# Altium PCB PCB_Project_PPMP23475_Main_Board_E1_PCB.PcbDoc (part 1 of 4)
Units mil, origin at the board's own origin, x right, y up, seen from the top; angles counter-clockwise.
Board outline 10826.77 x 2559.06 mil, 6 copper layers (Top Layer, Signal Layer 1, Signal Layer 2, Signal Layer 3, Signal Layer 4, Bottom Layer), stack 65.535 mil thick; 162 components, 91 nets, 425 pads, 676 vias.
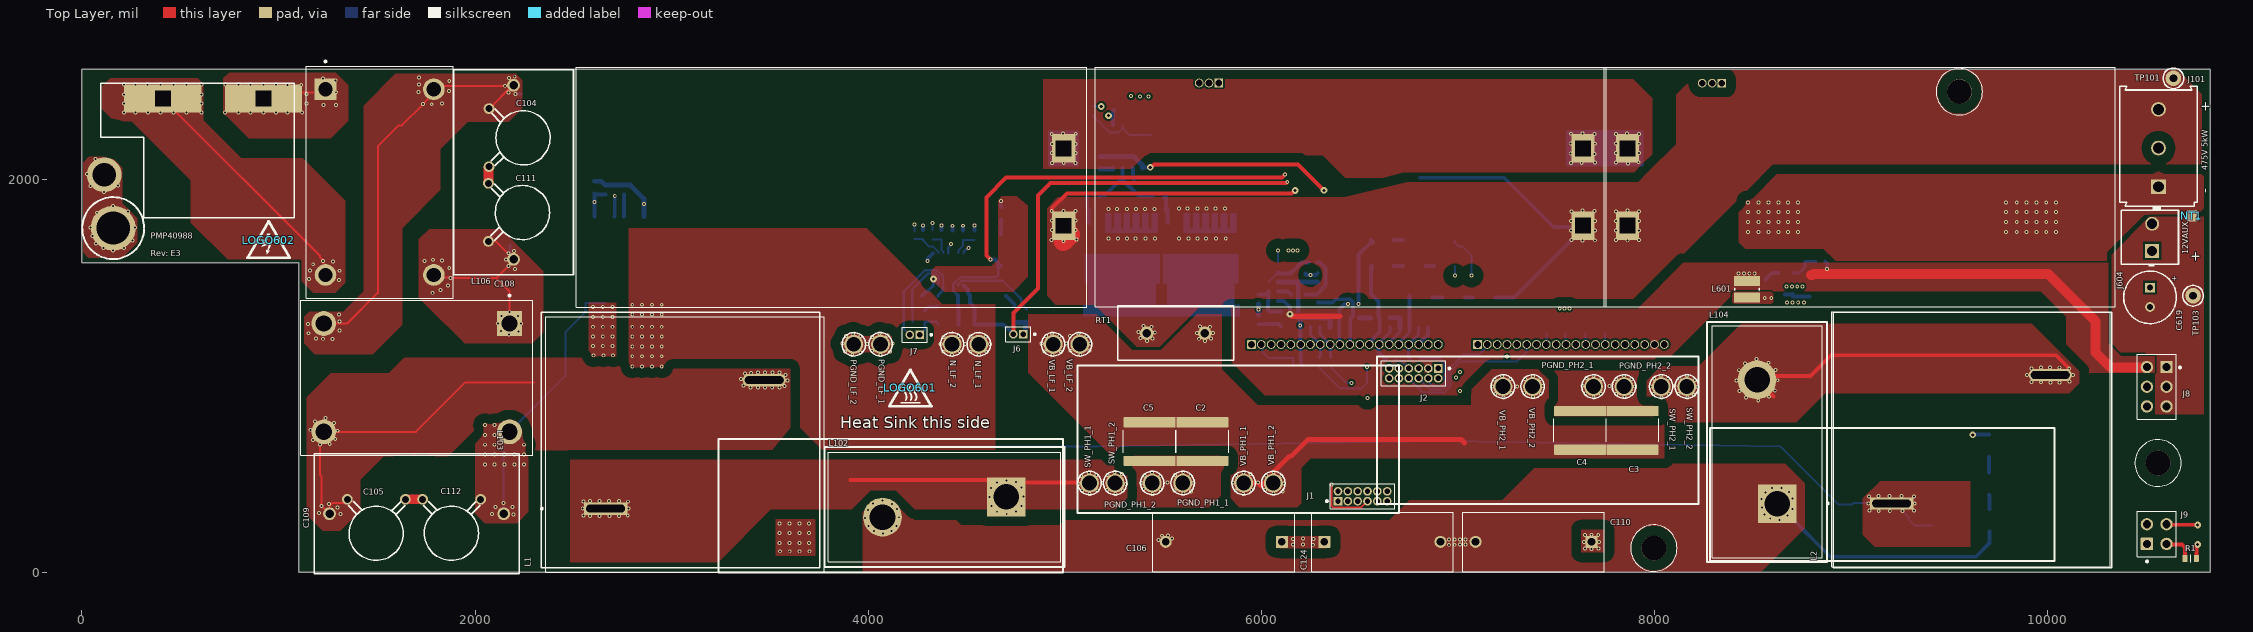
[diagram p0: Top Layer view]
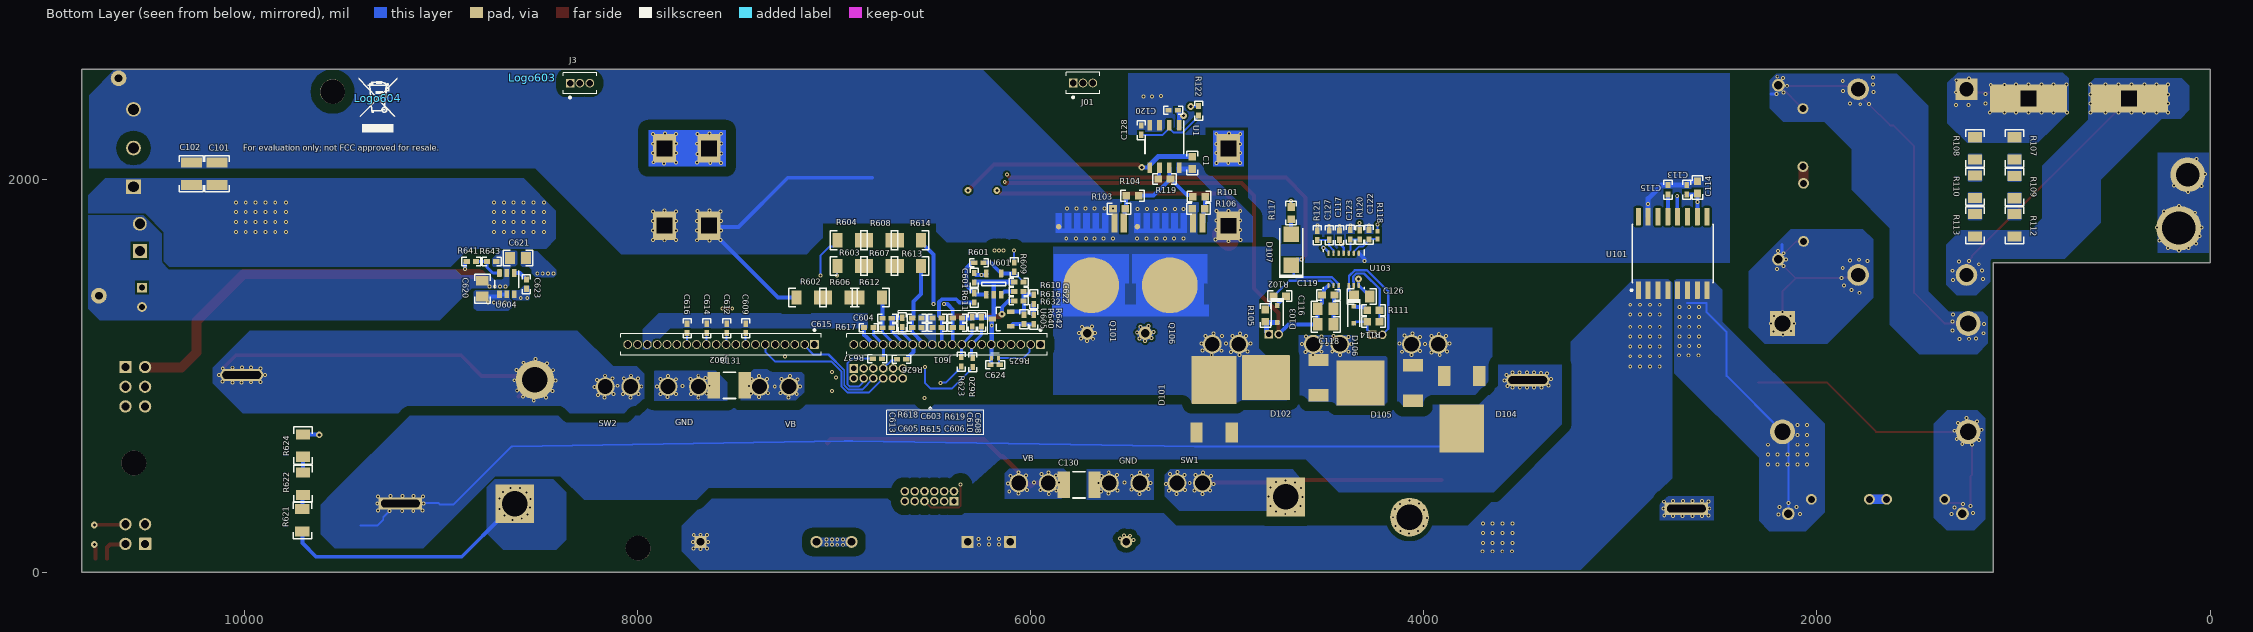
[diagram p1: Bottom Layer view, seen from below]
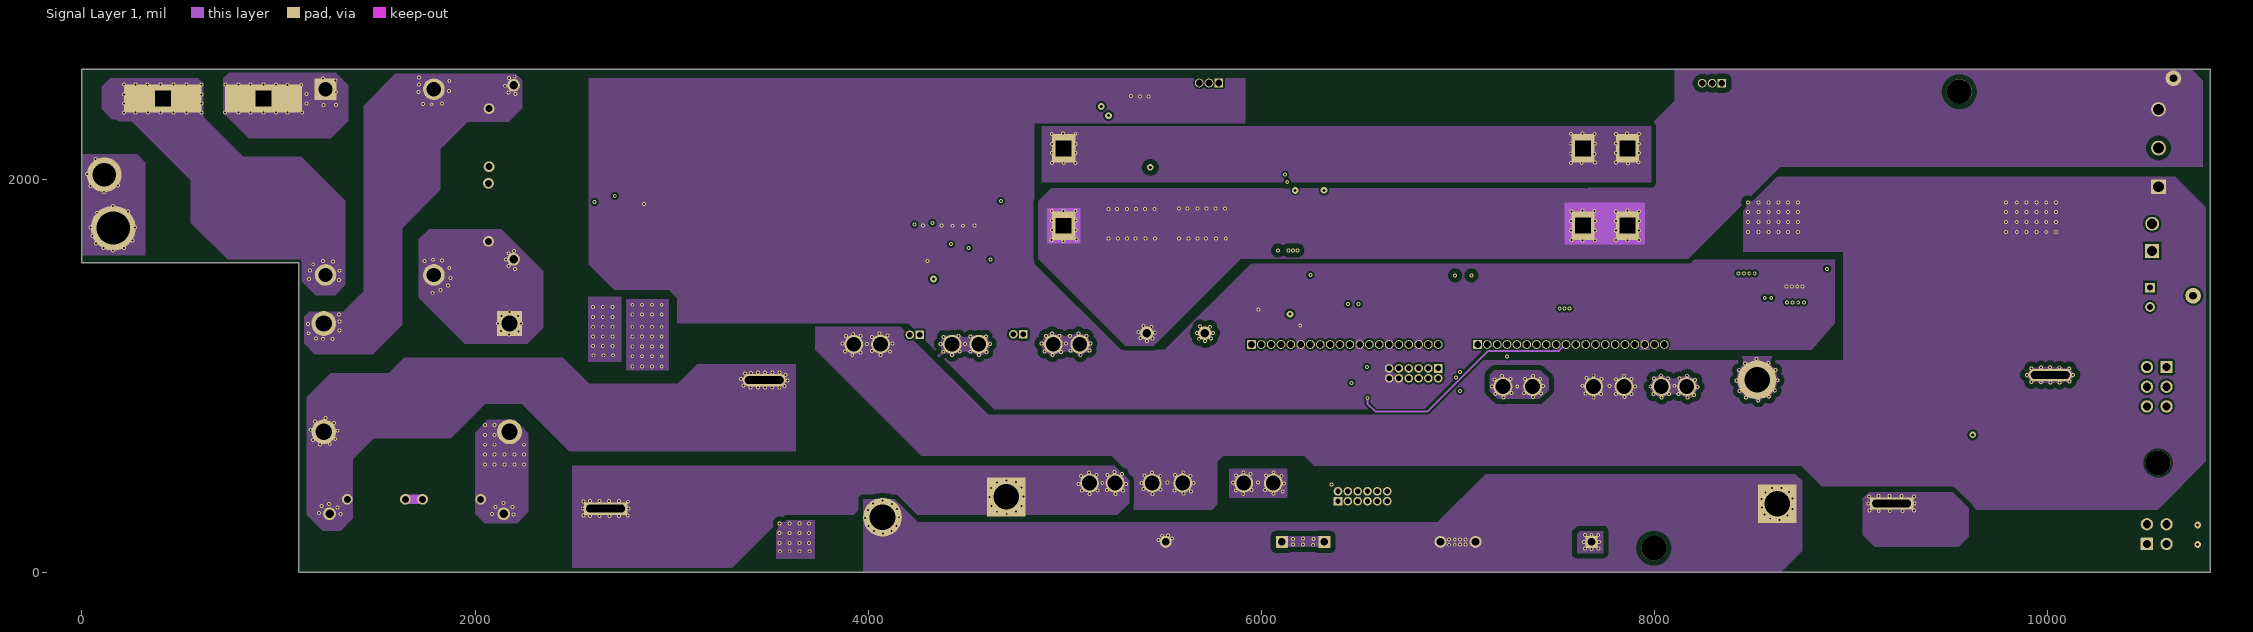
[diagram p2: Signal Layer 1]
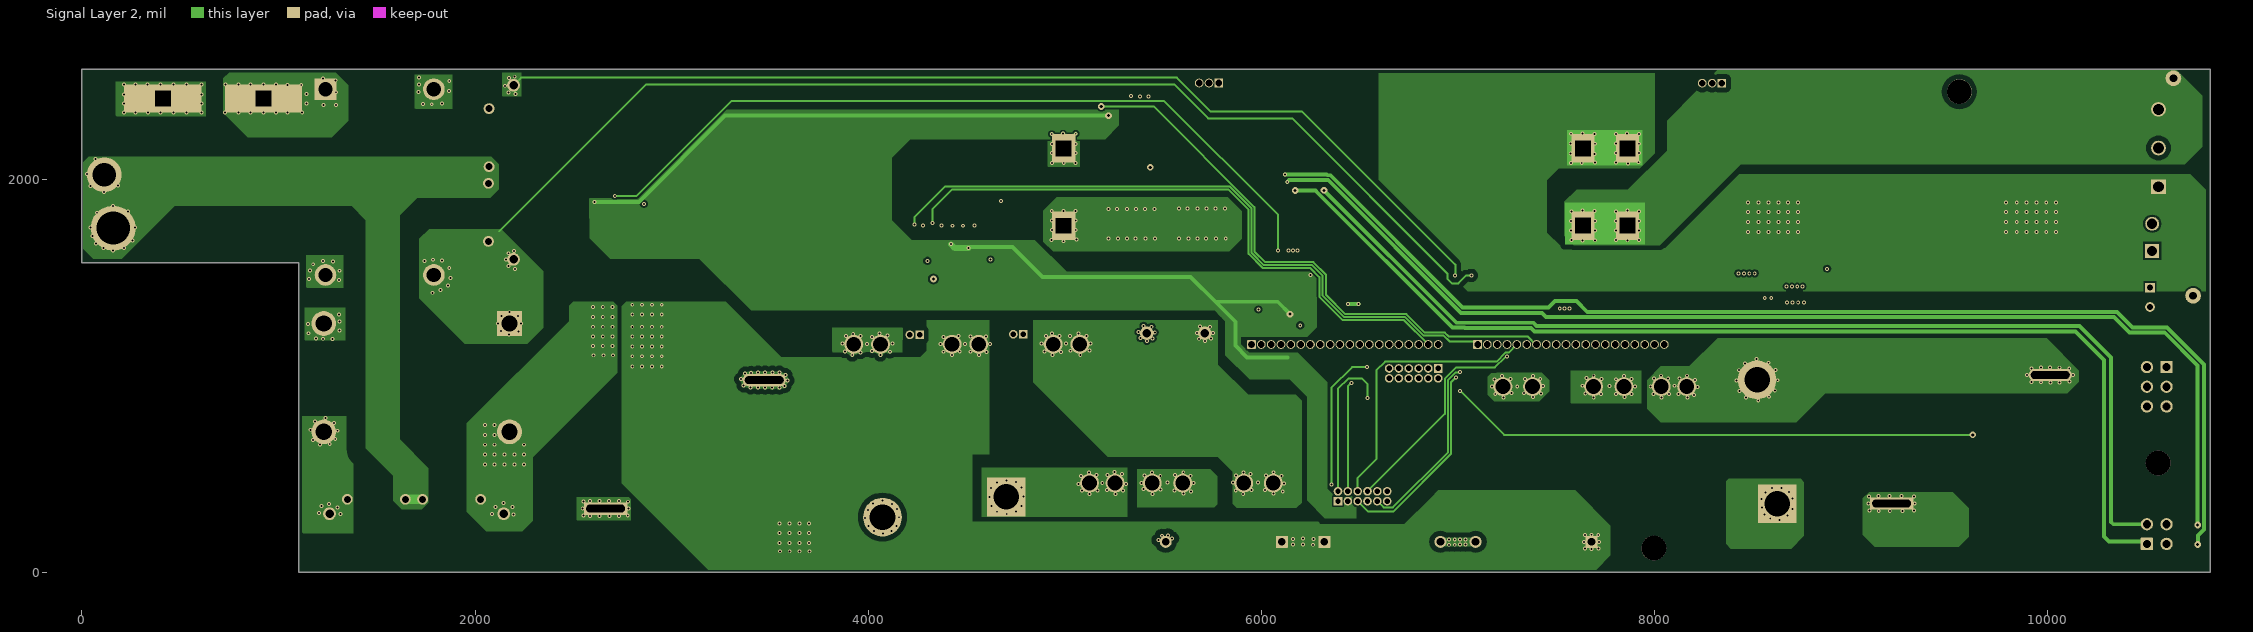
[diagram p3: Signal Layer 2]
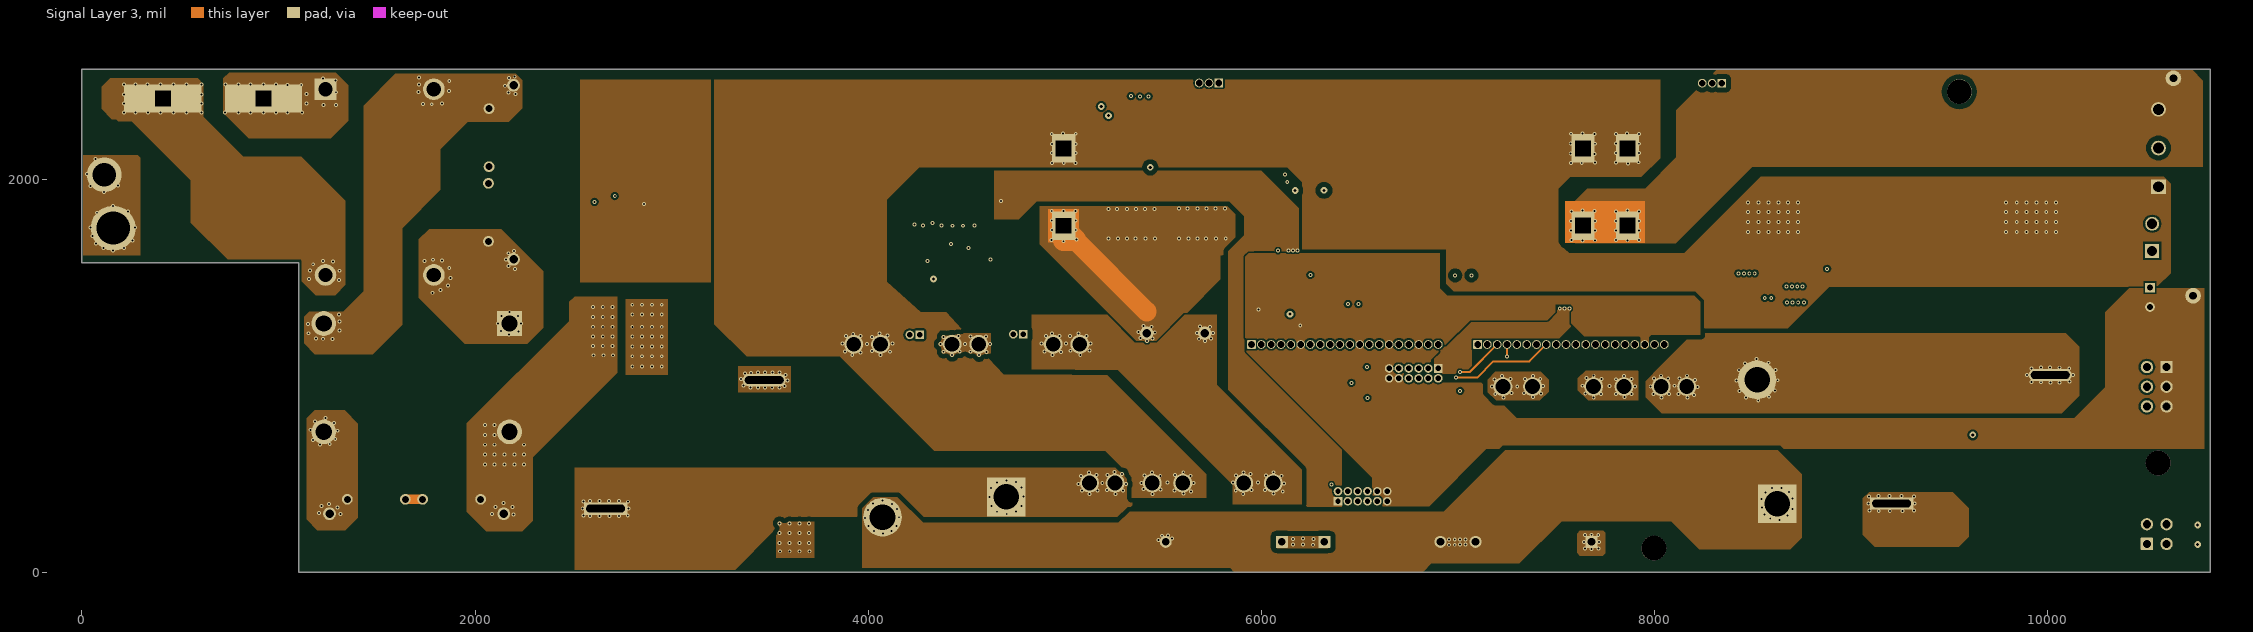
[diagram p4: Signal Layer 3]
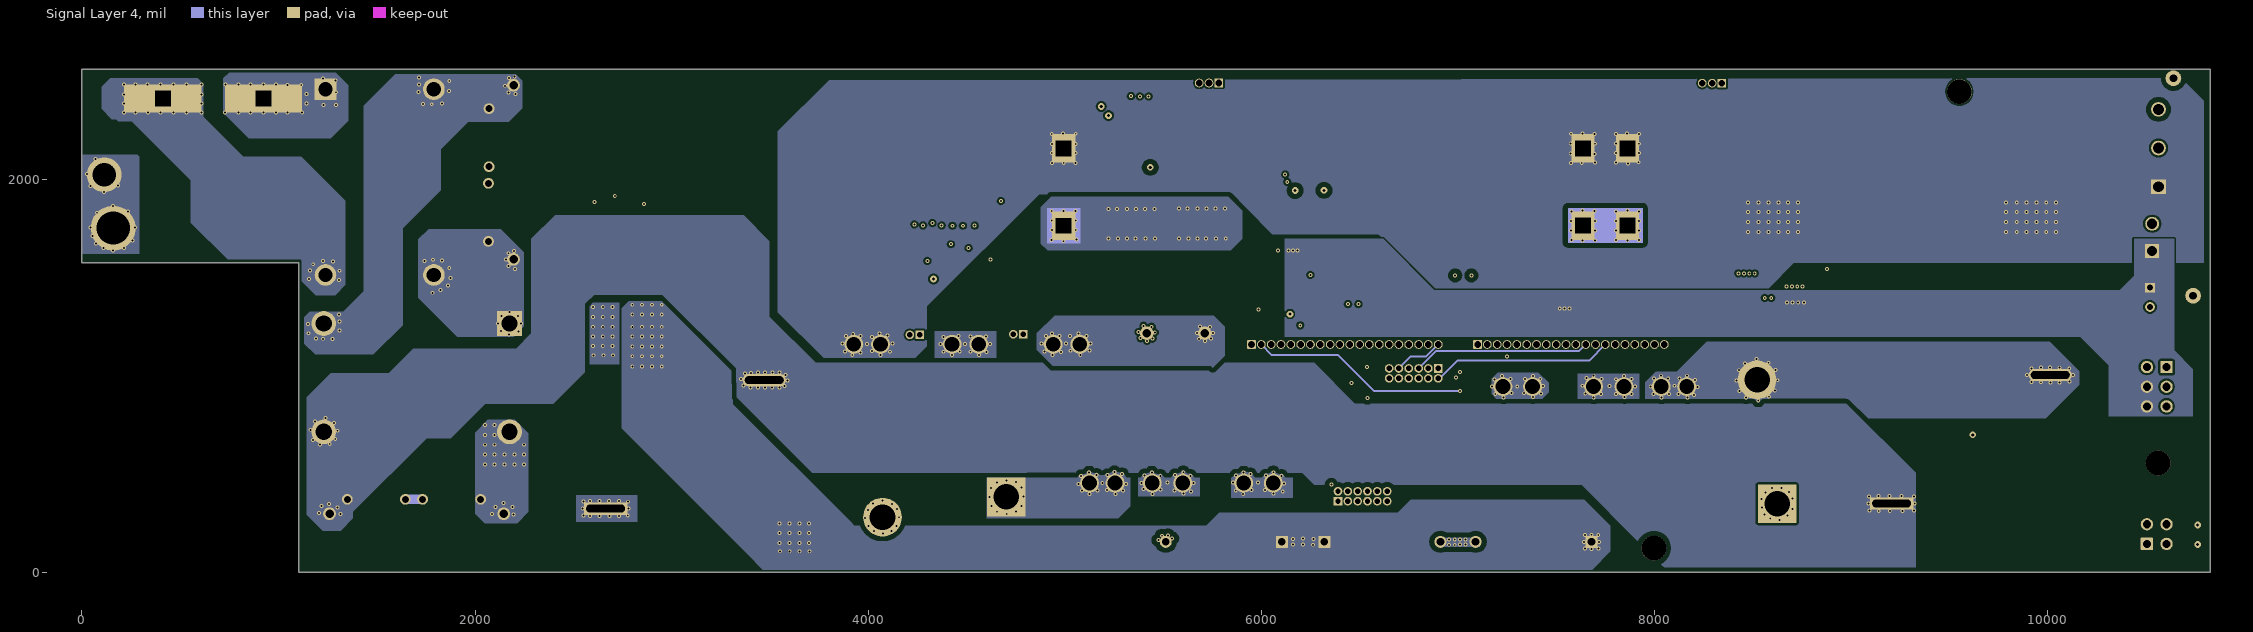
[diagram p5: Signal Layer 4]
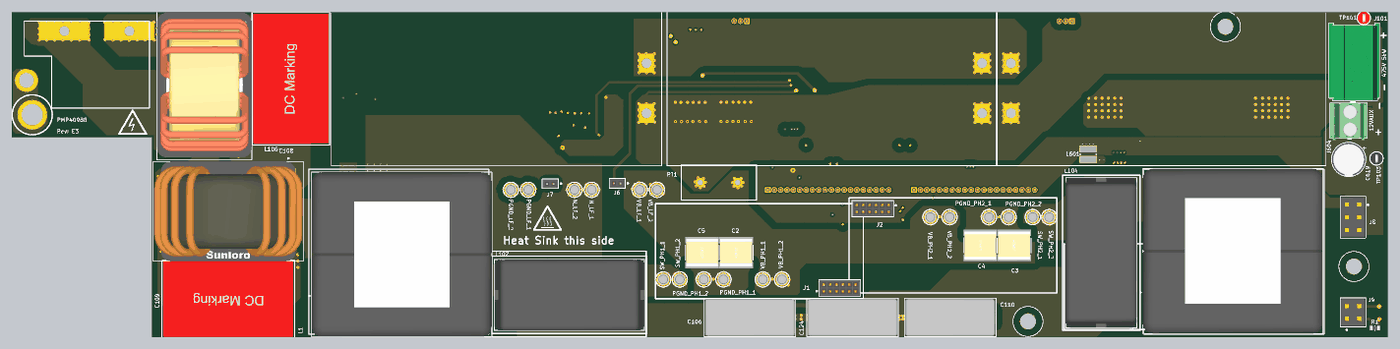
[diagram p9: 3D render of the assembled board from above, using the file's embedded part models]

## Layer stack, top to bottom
Top Solder: solder mask 0.4, Solder Resist, Dk 3.5
Top Layer: signal copper 2.7559
Dielectric1: prepreg 7, Dk 4.2
Signal Layer 1: signal copper 2.7559
Dielectric 3: core 14, FR-4, Dk 4.2
Signal Layer 2: signal copper 2.7559
Dielectric 4: prepreg 7, Dk 4.2
Signal Layer 3: signal copper 2.7559
Dielectric 5: core 14, FR-4, Dk 4.2
Signal Layer 4: signal copper 2.7559
Dielectric 2: prepreg 7, Dk 4.2
Bottom Layer: signal copper 2.7559
Bottom Solder: solder mask 0.4, Solder Resist, Dk 3.5

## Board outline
0,1574.8 1102.36,1574.8 1102.36,0 10826.77,0 10826.77,2559.06 0,2559.06

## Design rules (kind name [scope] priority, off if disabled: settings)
AcuteAngle [All] p1: minimum=4.50000000000000E+0001 checktracksonly=FALSE
AssemblyTestPointUsage [All] p1: valid=2
Clearance Clearance_Earth_Top_Layer [InNet('EARTH') vs Not InNet('EARTH') And OnLayer('Top Layer')] p1: gap=200 ignorepadtopadclearanceinfootprint=TRUE
Clearance Clearance_Earth_Mid_Layer [InNet('EARTH') vs Not InNet('EARTH') And (OnMultiLayer Or OnMid)] p2: gap=100 ignorepadtopadclearanceinfootprint=TRUE
Clearance Clearance_LF_Bridge_Exception [InNet('-BRDG_P') vs InNet('VDDB')] p3: gap=35 ignorepadtopadclearanceinfootprint=TRUE
Clearance Clearance_HV_DC_Outer [InNetClass('HV_DC') And OnOutside vs Not (InNetClass('HV_DC') or InNetClass('HV_AC_LF_SW'))] p4: gap=50 ignorepadtopadclearanceinfootprint=TRUE
Clearance Clearance_HV_DC_Inner [InNetClass('HV_DC') And (OnMultiLayer Or OnMid) vs Not InNetClass('HV_DC')] p5: gap=25 ignorepadtopadclearanceinfootprint=TRUE
Clearance Clearance_HV_AC_L_Outer [InNetClass('HV_AC_L') And OnOutside vs Not (InNetClass('HV_AC_L') Or InNetClass('HV_AC_LF_SW'))] p6: gap=50 ignorepadtopadclearanceinfootprint=TRUE
Clearance Clearance_HV_AC_L_Inner [InNetClass('HV_AC_L') And (OnMultiLayer Or OnMid) vs Not (InNetClass('HV_AC_L') Or InNetClass('HV_AC_LF_SW'))] p7: gap=25 ignorepadtopadclearanceinfootprint=TRUE
Clearance Clearance_HV_AC_N_Outer [InNetClass('HV_AC_N') And OnOutside vs Not (InNetClass('HV_AC_N') Or InNetClass('HV_AC_LF_SW'))] p8: gap=50 ignorepadtopadclearanceinfootprint=TRUE
Clearance Clearance_HV_AC_N_Inner [InNetClass('HV_AC_N') And (OnMultiLayer Or OnMid) vs Not (InNetClass('HV_AC_N') Or InNetClass('HV_AC_LF_SW'))] p9: gap=25 ignorepadtopadclearanceinfootprint=TRUE
Clearance Clearance_HV_SW_Outer [InNetClass('HV_SW') And OnOutside] p10: gap=50 ignorepadtopadclearanceinfootprint=TRUE
Clearance Clearance_HV_SW_Inner [InNetClass('HV_SW') And (OnMultiLayer Or OnMid)] p11: gap=25 ignorepadtopadclearanceinfootprint=TRUE
Clearance Clearance_Keepouts [((IsTrack Or IsArc) And Not InPoly) And IsFree and IsKeepOut vs ((IsTrack Or IsArc) And Not InPoly) And IsFree and IsKeepOut] p12: gap=0 ignorepadtopadclearanceinfootprint=FALSE
Clearance Clearance_BoardEdge_MountingHoles [OnCopper and InComponentClass('Mounting Holes') vs IsKeepOut] p13: gap=40 ignorepadtopadclearanceinfootprint=FALSE
Clearance Clearance_BoardEdge_Poly [OnCopper and InPoly vs IsKeepOut] p14: gap=25 ignorepadtopadclearanceinfootprint=FALSE
Clearance Clearance_BoardEdge [OnCopper and Not InComponentClass('Logo') and not InComponentClass('FiducialMark') and not InRegion(1000,500,4000,800) and Not IsKeepout vs IsKeepOut] p15: gap=75 ignorepadtopadclearanceinfootprint=FALSE
Clearance Clearance_Poly [InPolygon] p16: gap=10 ignorepadtopadclearanceinfootprint=FALSE
Clearance [All] p17: gap=5 ignorepadtopadclearanceinfootprint=TRUE
ComponentClearance ComponentClearance_PMP23209 [InNamedUnion('PMP23209') vs InNamedUnion('PMP23209')] p1: gap=0 collisioncheckmode=3 verticalgap=0 showdistances=FALSE
ComponentClearance ComponentClearance_GaN_DC_PH1 [(InNamedUnion('GaN Daughter Card Phase 1')) vs (InNamedUnion('GaN Daughter Card Phase 1'))] p2: gap=0 collisioncheckmode=3 verticalgap=0 showdistances=FALSE
ComponentClearance ComponentClearance_GaN_DC_PH2 [(InNamedUnion('GaN Daughter Card Phase 2')) vs (InNamedUnion('GaN Daughter Card Phase 2'))] p3: gap=0 collisioncheckmode=3 verticalgap=0 showdistances=FALSE
ComponentClearance ComponentClearance_LF_DC [(InNamedUnion('Low Frequency Daughter Card')) vs (InNamedUnion('Low Frequency Daughter Card'))] p4: gap=0 collisioncheckmode=3 verticalgap=0 showdistances=FALSE
ComponentClearance ComponentClearance_Control_Card [InNamedUnion('Control Card') vs InNamedUnion('Control Card')] p5: gap=0 collisioncheckmode=3 verticalgap=0 showdistances=FALSE
ComponentClearance ComponentClearance_Bulk_Caps [(ObjectKind = '3D Body') And (Identifier = 'PCB_Project_PMP40988_Bulk_Cap_1_E2') vs (ObjectKind = '3D Body') And (Identifier = 'PCB_Project_PMP40988_Bulk_Cap_2_E2')] p6: gap=0 collisioncheckmode=3 verticalgap=0 showdistances=FALSE
ComponentClearance ComponentClearance_MountingHoles_FiducialMarks [InComponentClass('Mounting Holes') vs InComponentClass('FiducialMark')] p7: gap=20 collisioncheckmode=3 verticalgap=10 showdistances=FALSE
ComponentClearance ComponentClearance_Shunt [InComponentClass('Header') vs InComponentClass('Shunt')] p8: gap=0 collisioncheckmode=3 verticalgap=0 showdistances=FALSE
ComponentClearance ComponentClearance_Logo [InComponentClass('Logo')] p9: gap=5 collisioncheckmode=3 verticalgap=10 showdistances=FALSE
ComponentClearance ComponentClearance_ScrewToNut [(HasFootprint('NY PMS 440 0025 PH')) vs (HasFootprint('Keystone_1902C'))] p10: gap=20 collisioncheckmode=3 verticalgap=100000 showdistances=FALSE
ComponentClearance ComponentClearance_MountingHoles [InComponentClass('Mounting Holes')] p11: gap=20 collisioncheckmode=3 verticalgap=10 showdistances=FALSE
ComponentClearance ComponentClearance_SmallPassives [HasFootprint('0201*') or HasFootprint('0402*') or HasFootprint('0508') or HasFootprint('0603*') or HasFootprint('0612') or HasFootprint('0805*') or HasFootprint('0815*') or HasFootprint('0830*') or HasFootprint('1206*') or HasFootprint('1210*') or HasFootprint('1808*') or HasFootprint('1812*') or HasFootprint('1825*') or HasFootprint('2010*') or HasFootprint('2220*') or HasFootprint('2225*') or HasFootprint('2512*') or HasFootprint('2728*') or HasFootprint('3518*') vs HasFootprint('0201*') or HasFootprint('0402*') or HasFootprint('0508') or HasFootprint('0603*') or HasFootprint('0612') or HasFootprint('0805*') or HasFootprint('0815*') or HasFootprint('0830*') or HasFootprint('1206*') or HasFootprint('1210*') or HasFootprint('1808*') or HasFootprint('1812*') or HasFootprint('1825*') or HasFootprint('2010*') or HasFootprint('2220*') or HasFootprint('2225*') or HasFootprint('2512*') or HasFootprint('2728*') or HasFootprint('3518*')] p12: gap=20 collisioncheckmode=3 verticalgap=20 showdistances=FALSE
ComponentClearance ComponentClearance_THtoSMT [IsThruComponent vs IsSMTComponent] p13: gap=10 collisioncheckmode=3 verticalgap=10 showdistances=FALSE
ComponentClearance ComponentClearance_THtoTH [IsThruComponent vs IsThruComponent] p14: gap=10 collisioncheckmode=3 verticalgap=10 showdistances=FALSE
ComponentClearance [All] p15: gap=10 collisioncheckmode=3 verticalgap=10 showdistances=FALSE
DiffPairsRouting [All] p1: maxlimit=100 minlimit=10 mostfreqgap=10 toplayer_minwidth=15 toplayer_maxwidth=15 toplayer_prefwidth=15 midlayer1_minwidth=15 midlayer1_maxwidth=15 midlayer1_prefwidth=15 midlayer2_minwidth=15 midlayer2_maxwidth=15 midlayer2_prefwidth=15 midlayer3_minwidth=15 midlayer3_maxwidth=15 midlayer3_prefwidth=15 midlayer4_minwidth=15 midlayer4_maxwidth=15 midlayer4_prefwidth=15 bottomlayer_minwidth=15 bottomlayer_maxwidth=15 bottomlayer_prefwidth=15 maxuncoupledlength=1000
FabricationTestPointUsage TestPointUsage [All] p1: valid=2 allowmultiple=FALSE
FabricationTestpoint Testpoint [All] p1: side=3 testpointundercomponent=TRUE minsize=40 maxsize=100 preferedsize=60 minholesize=0 maxholesize=40 preferedholesize=32 testpointgrid=1 allowsidetop=TRUE allowsidebottom=TRUE usegrid=TRUE gridtolerance=0.01
FanoutControl Fanout_LCC [IsLCC] p1: bgadir=Out bgaviamode=Centered fanoutstyle=Auto fanoutdirection=Alternating viagrid=1 // Fanout_LCC (Default Rule)
FanoutControl Fanout_BGA [IsBGA] p2: bgadir=Out bgaviamode=Centered fanoutstyle=Auto fanoutdirection=Alternating viagrid=1 // Fanout_BGA (Default Rule)
FanoutControl Fanout_Default [All] p4: bgadir=Out bgaviamode=Centered fanoutstyle=Auto fanoutdirection=Alternating viagrid=1 // Fanout_Default (Default Rule)
FanoutControl Fanout_Small [(CompPinCount < 5)] p5: bgadir=Out bgaviamode=Centered fanoutstyle=Auto fanoutdirection=OutThenIn viagrid=1 // Fanout_Small (Default Rule)
Height [All] p1: minheight=0 maxheight=1299.21 prefheight=500
HoleSize [All] p1: absolutevalues=TRUE maxlimit=400 minlimit=7 maxpercent=80.000 minpercent=20.000
MinimumAnnularRing MinimumAnnularRing_ThermalPadVias [IsVia and InAnyComponent] p1: minimumring=5.91
MinimumAnnularRing MinimumAnnularRing_StandOff_Mount [(ObjectKind = 'Pad') And (Net = 'No Net') And (Component = 'Free')] p2: minimumring=0
MinimumAnnularRing [All] p3: minimumring=4.9
MinimumSolderMaskSliver MinimumSolderMaskSliver_Logo [InComponentClass('Logo') vs InComponentClass('Logo')] p1: minsoldermaskwidth=0.7
MinimumSolderMaskSliver [All] p2: minsoldermaskwidth=2
PlaneConnect [All] p1: planeconnectstyle=Direct reliefexpansion=10 reliefentries=4 reliefconductorwidth=10 reliefairgap=10
PolygonConnect PolygonConnect_26 [All vs IsNamedPolygon('12VP') Or  IsNamedPolygon('D106_1') Or  IsNamedPolygon('HVBUS') Or  IsNamedPolygon('Earth') Or  IsNamedPolygon('L101_1') Or  IsNamedPolygon('C110_2') Or  IsNamedPolygon('Earth') Or  IsNamedPolygon('SWNODE3') Or  IsNamedPolygon('C107_1') Or  IsNamedPolygon('L102_1') Or  IsNamedPolygon('L100_1') Or  IsNamedPolygon('AC_N') Or  IsNamedPolygon('C109_1') Or  IsNamedPolygon('Earth') Or  IsNamedPolygon('C109_1') Or  IsNamedPolygon('F100_2') Or  IsNamedPolygon('-BRDG_N') Or  IsNamedPolygon('C109_1') Or  IsNamedPolygon('-BRDG_N') Or  IsNamedPolygon('Earth') Or  IsNamedPolygon('C113_2') Or  IsNamedPolygon('Earth') Or  IsNamedPolygon('C110_2') Or  IsNamedPolygon('C107_1') Or  IsNamedPolygon('SWNODE2') Or  IsNamedPolygon('SGND2') Or  IsNamedPolygon('C113_2') Or  IsNamedPolygon('C109_2') Or  IsNamedPolygon('L101_1') Or  IsNamedPolygon('AC_N') Or  IsNamedPolygon('C113_2') Or  IsNamedPolygon('SWNODE2') Or  IsNamedPolygon('-BRDG_N') Or  IsNamedPolygon('C113_2') Or  IsNamedPolygon('AC_N') Or  IsNamedPolygon('5VS') Or  IsNamedPolygon('C110_2') Or  IsNamedPolygon('PGND') Or  IsNamedPolygon('HVBUS') Or  IsNamedPolygon('C107_1') Or  IsNamedPolygon('F100_2') Or  IsNamedPolygon('AC_L') Or  IsNamedPolygon('SGND2') Or  IsNamedPolygon('-BRDG_N') Or  IsNamedPolygon('C109_1') Or  IsNamedPolygon('L101_1') Or  IsNamedPolygon('C109_2') Or  IsNamedPolygon('C110_2') Or  IsNamedPolygon('C109_2') Or  IsNamedPolygon('-BRDG_N') Or  IsNamedPolygon('C110_2') Or  IsNamedPolygon('C109_1') Or  IsNamedPolygon('C109_2') Or  IsNamedPolygon('F100_2') Or  IsNamedPolygon('AC_N') Or  IsNamedPolygon('C109_2') Or  IsNamedPolygon('F100_2') Or  IsNamedPolygon('C107_1') Or  IsNamedPolygon('C113_2') Or  IsNamedPolygon('F100_2') Or  IsNamedPolygon('AC_N') Or  IsNamedPolygon('C110_2') Or  IsNamedPolygon('SWNODE1') Or  IsNamedPolygon('C109_2') Or  IsNamedPolygon('C109_1') Or  IsNamedPolygon('C107_1') Or  IsNamedPolygon('F100_2') Or  IsNamedPolygon('C107_1') Or  IsNamedPolygon('AC_N') Or  IsNamedPolygon('L100_1') Or  IsNamedPolygon('Earth') Or  IsNamedPolygon('C113_2') Or  IsNamedPolygon('SWNODE1') Or  IsNamedPolygon('AC_L') Or  IsNamedPolygon('L102_1') Or  IsNamedPolygon('SWNODE3') Or  IsNamedPolygon('AC_L')] p1: connectstyle=Direct reliefconductorwidth=10 reliefentries=4 polygonreliefangle="90 Angle" airgapwidth=10
PolygonConnect PolygonConnect_25 [All vs IsNamedPolygon('12VP') Or  IsNamedPolygon('SWNODE2') Or  IsNamedPolygon('F100_2') Or  IsNamedPolygon('AC_N') Or  IsNamedPolygon('C113_2') Or  IsNamedPolygon('-BRDG_N') Or  IsNamedPolygon('L102_1') Or  IsNamedPolygon('Earth') Or  IsNamedPolygon('SWNODE3') Or  IsNamedPolygon('L101_1') Or  IsNamedPolygon('C109_2') Or  IsNamedPolygon('C107_1') Or  IsNamedPolygon('C110_2') Or  IsNamedPolygon('C109_2') Or  IsNamedPolygon('C110_2') Or  IsNamedPolygon('5VS') Or  IsNamedPolygon('L101_1') Or  IsNamedPolygon('-BRDG_N') Or  IsNamedPolygon('AC_L') Or  IsNamedPolygon('AC_N') Or  IsNamedPolygon('F100_2') Or  IsNamedPolygon('AC_N') Or  IsNamedPolygon('-BRDG_N') Or  IsNamedPolygon('AC_L') Or  IsNamedPolygon('L102_1') Or  IsNamedPolygon('C109_2') Or  IsNamedPolygon('L100_1') Or  IsNamedPolygon('C113_2') Or  IsNamedPolygon('C113_2') Or  IsNamedPolygon('C113_2') Or  IsNamedPolygon('C109_2') Or  IsNamedPolygon('Earth') Or  IsNamedPolygon('AC_N') Or  IsNamedPolygon('C107_1') Or  IsNamedPolygon('C107_1') Or  IsNamedPolygon('F100_2') Or  IsNamedPolygon('C109_1') Or  IsNamedPolygon('-BRDG_N') Or  IsNamedPolygon('C110_2') Or  IsNamedPolygon('AC_L') Or  IsNamedPolygon('C113_2') Or  IsNamedPolygon('Earth') Or  IsNamedPolygon('C109_1') Or  IsNamedPolygon('C110_2') Or  IsNamedPolygon('SWNODE3') Or  IsNamedPolygon('C109_1') Or  IsNamedPolygon('C109_2') Or  IsNamedPolygon('C107_1') Or  IsNamedPolygon('F100_2') Or  IsNamedPolygon('D106_1') Or  IsNamedPolygon('C109_1') Or  IsNamedPolygon('L101_1') Or  IsNamedPolygon('C110_2') Or  IsNamedPolygon('C107_1') Or  IsNamedPolygon('C109_2') Or  IsNamedPolygon('C109_1') Or  IsNamedPolygon('Earth') Or  IsNamedPolygon('HVBUS') Or  IsNamedPolygon('Earth') Or  IsNamedPolygon('AC_N') Or  IsNamedPolygon('SWNODE2') Or  IsNamedPolygon('AC_N') Or  IsNamedPolygon('Earth') Or  IsNamedPolygon('F100_2') Or  IsNamedPolygon('C110_2') Or  IsNamedPolygon('F100_2') Or  IsNamedPolygon('SWNODE1') Or  IsNamedPolygon('C113_2') Or  IsNamedPolygon('C107_1') Or  IsNamedPolygon('C109_1') Or  IsNamedPolygon('L100_1') Or  IsNamedPolygon('-BRDG_N') Or  IsNamedPolygon('SWNODE1')] p2: connectstyle=Direct reliefconductorwidth=10 reliefentries=4 polygonreliefangle="90 Angle" airgapwidth=10
PolygonConnect PolygonConnect_24 [All vs IsNamedPolygon('12VP') Or  IsNamedPolygon('C113_2') Or  IsNamedPolygon('C107_1') Or  IsNamedPolygon('L100_1') Or  IsNamedPolygon('C107_1') Or  IsNamedPolygon('C107_1') Or  IsNamedPolygon('5VS') Or  IsNamedPolygon('C113_2') Or  IsNamedPolygon('SWNODE3') Or  IsNamedPolygon('AC_N') Or  IsNamedPolygon('C113_2') Or  IsNamedPolygon('C113_2') Or  IsNamedPolygon('C109_2') Or  IsNamedPolygon('F100_2') Or  IsNamedPolygon('F100_2') Or  IsNamedPolygon('C113_2') Or  IsNamedPolygon('Earth') Or  IsNamedPolygon('C109_2') Or  IsNamedPolygon('C109_1') Or  IsNamedPolygon('C110_2') Or  IsNamedPolygon('-BRDG_N') Or  IsNamedPolygon('AC_N') Or  IsNamedPolygon('C110_2') Or  IsNamedPolygon('L102_1') Or  IsNamedPolygon('AC_N') Or  IsNamedPolygon('D106_1') Or  IsNamedPolygon('L102_1') Or  IsNamedPolygon('Earth') Or  IsNamedPolygon('F100_2') Or  IsNamedPolygon('-BRDG_N') Or  IsNamedPolygon('C109_1') Or  IsNamedPolygon('SWNODE2') Or  IsNamedPolygon('C109_2') Or  IsNamedPolygon('SWNODE1') Or  IsNamedPolygon('-BRDG_N') Or  IsNamedPolygon('-BRDG_N') Or  IsNamedPolygon('-BRDG_N') Or  IsNamedPolygon('AC_N') Or  IsNamedPolygon('AC_L') Or  IsNamedPolygon('AC_L') Or  IsNamedPolygon('SWNODE3') Or  IsNamedPolygon('C113_2') Or  IsNamedPolygon('C109_1') Or  IsNamedPolygon('C109_2') Or  IsNamedPolygon('Earth') Or  IsNamedPolygon('SWNODE1') Or  IsNamedPolygon('C110_2') Or  IsNamedPolygon('SWNODE2') Or  IsNamedPolygon('F100_2') Or  IsNamedPolygon('C107_1') Or  IsNamedPolygon('F100_2') Or  IsNamedPolygon('L100_1') Or  IsNamedPolygon('C107_1') Or  IsNamedPolygon('C110_2') Or  IsNamedPolygon('L101_1') Or  IsNamedPolygon('C110_2') Or  IsNamedPolygon('AC_N') Or  IsNamedPolygon('C110_2') Or  IsNamedPolygon('Earth') Or  IsNamedPolygon('AC_N') Or  IsNamedPolygon('C109_2') Or  IsNamedPolygon('Earth') Or  IsNamedPolygon('C109_2') Or  IsNamedPolygon('C109_1') Or  IsNamedPolygon('C109_1') Or  IsNamedPolygon('C109_1') Or  IsNamedPolygon('C107_1') Or  IsNamedPolygon('L101_1') Or  IsNamedPolygon('L101_1') Or  IsNamedPolygon('F100_2') Or  IsNamedPolygon('Earth')] p3: connectstyle=Direct reliefconductorwidth=10 reliefentries=4 polygonreliefangle="90 Angle" airgapwidth=10
PolygonConnect PolygonConnect_23 [All vs IsNamedPolygon('C110_2') Or  IsNamedPolygon('C110_2') Or  IsNamedPolygon('C109_2') Or  IsNamedPolygon('C110_2') Or  IsNamedPolygon('C110_2') Or  IsNamedPolygon('C110_2') Or  IsNamedPolygon('C109_2') Or  IsNamedPolygon('12VP') Or  IsNamedPolygon('5VS') Or  IsNamedPolygon('D106_1') Or  IsNamedPolygon('C109_2') Or  IsNamedPolygon('C109_2') Or  IsNamedPolygon('C109_2') Or  IsNamedPolygon('C109_2') Or  IsNamedPolygon('C109_1') Or  IsNamedPolygon('F100_2') Or  IsNamedPolygon('C109_1') Or  IsNamedPolygon('Earth') Or  IsNamedPolygon('AC_N') Or  IsNamedPolygon('Earth') Or  IsNamedPolygon('F100_2') Or  IsNamedPolygon('C109_1') Or  IsNamedPolygon('Earth') Or  IsNamedPolygon('C109_1') Or  IsNamedPolygon('-BRDG_N') Or  IsNamedPolygon('C107_1') Or  IsNamedPolygon('AC_L') Or  IsNamedPolygon('C109_1') Or  IsNamedPolygon('SWNODE2') Or  IsNamedPolygon('C113_2') Or  IsNamedPolygon('SWNODE1') Or  IsNamedPolygon('-BRDG_N') Or  IsNamedPolygon('-BRDG_N') Or  IsNamedPolygon('Earth') Or  IsNamedPolygon('C107_1') Or  IsNamedPolygon('SWNODE1') Or  IsNamedPolygon('F100_2') Or  IsNamedPolygon('-BRDG_N') Or  IsNamedPolygon('C107_1') Or  IsNamedPolygon('AC_N') Or  IsNamedPolygon('AC_N') Or  IsNamedPolygon('Earth') Or  IsNamedPolygon('-BRDG_N') Or  IsNamedPolygon('C107_1') Or  IsNamedPolygon('SWNODE3') Or  IsNamedPolygon('C107_1') Or  IsNamedPolygon('C113_2') Or  IsNamedPolygon('F100_2') Or  IsNamedPolygon('SWNODE3') Or  IsNamedPolygon('Earth') Or  IsNamedPolygon('C109_1') Or  IsNamedPolygon('C113_2') Or  IsNamedPolygon('F100_2') Or  IsNamedPolygon('C113_2') Or  IsNamedPolygon('C110_2') Or  IsNamedPolygon('AC_L') Or  IsNamedPolygon('AC_N') Or  IsNamedPolygon('AC_N') Or  IsNamedPolygon('AC_N') Or  IsNamedPolygon('SWNODE2') Or  IsNamedPolygon('F100_2') Or  IsNamedPolygon('C113_2') Or  IsNamedPolygon('AC_N') Or  IsNamedPolygon('-BRDG_N') Or  IsNamedPolygon('C107_1') Or  IsNamedPolygon('C113_2')] p4: connectstyle=Direct reliefconductorwidth=10 reliefentries=4 polygonreliefangle="90 Angle" airgapwidth=10
PolygonConnect PolygonConnect_22 [All vs IsNamedPolygon('12VP') Or  IsNamedPolygon('C107_1') Or  IsNamedPolygon('C107_1') Or  IsNamedPolygon('C109_1') Or  IsNamedPolygon('Earth') Or  IsNamedPolygon('Earth') Or  IsNamedPolygon('Earth') Or  IsNamedPolygon('C109_1') Or  IsNamedPolygon('C107_1') Or  IsNamedPolygon('C109_1') Or  IsNamedPolygon('Earth') Or  IsNamedPolygon('Earth') Or  IsNamedPolygon('C109_1') Or  IsNamedPolygon('AC_L') Or  IsNamedPolygon('C107_1') Or  IsNamedPolygon('C107_1') Or  IsNamedPolygon('AC_L') Or  IsNamedPolygon('C107_1') Or  IsNamedPolygon('Earth') Or  IsNamedPolygon('AC_N') Or  IsNamedPolygon('C113_2') Or  IsNamedPolygon('C110_2') Or  IsNamedPolygon('C109_1') Or  IsNamedPolygon('F100_2') Or  IsNamedPolygon('C110_2') Or  IsNamedPolygon('C113_2') Or  IsNamedPolygon('AC_N') Or  IsNamedPolygon('-BRDG_N') Or  IsNamedPolygon('AC_N') Or  IsNamedPolygon('F100_2') Or  IsNamedPolygon('C110_2') Or  IsNamedPolygon('F100_2') Or  IsNamedPolygon('-BRDG_N') Or  IsNamedPolygon('C113_2') Or  IsNamedPolygon('C110_2') Or  IsNamedPolygon('-BRDG_N') Or  IsNamedPolygon('AC_N') Or  IsNamedPolygon('C113_2') Or  IsNamedPolygon('F100_2') Or  IsNamedPolygon('F100_2') Or  IsNamedPolygon('F100_2') Or  IsNamedPolygon('AC_N') Or  IsNamedPolygon('C110_2') Or  IsNamedPolygon('AC_N') Or  IsNamedPolygon('-BRDG_N') Or  IsNamedPolygon('AC_N') Or  IsNamedPolygon('-BRDG_N') Or  IsNamedPolygon('-BRDG_N') Or  IsNamedPolygon('C109_1') Or  IsNamedPolygon('C113_2') Or  IsNamedPolygon('C113_2') Or  IsNamedPolygon('C109_2') Or  IsNamedPolygon('C109_2') Or  IsNamedPolygon('C109_2') Or  IsNamedPolygon('5VS') Or  IsNamedPolygon('C110_2') Or  IsNamedPolygon('D106_1') Or  IsNamedPolygon('C109_2') Or  IsNamedPolygon('C109_2') Or  IsNamedPolygon('C109_2')] p5: connectstyle=Direct reliefconductorwidth=10 reliefentries=4 polygonreliefangle="90 Angle" airgapwidth=10
PolygonConnect PolygonConnect_21 [All vs IsNamedPolygon('C110_2') Or  IsNamedPolygon('C113_2') Or  IsNamedPolygon('C113_2') Or  IsNamedPolygon('C113_2') Or  IsNamedPolygon('C110_2') Or  IsNamedPolygon('C109_2') Or  IsNamedPolygon('C109_2') Or  IsNamedPolygon('C110_2') Or  IsNamedPolygon('D106_1') Or  IsNamedPolygon('C110_2') Or  IsNamedPolygon('C109_2') Or  IsNamedPolygon('C113_2') Or  IsNamedPolygon('C109_2') Or  IsNamedPolygon('5VS') Or  IsNamedPolygon('C109_2') Or  IsNamedPolygon('C110_2') Or  IsNamedPolygon('C109_2') Or  IsNamedPolygon('C110_2') Or  IsNamedPolygon('12VP') Or  IsNamedPolygon('C113_2') Or  IsNamedPolygon('C107_1') Or  IsNamedPolygon('AC_N') Or  IsNamedPolygon('C107_1') Or  IsNamedPolygon('C109_1') Or  IsNamedPolygon('Earth') Or  IsNamedPolygon('F100_2') Or  IsNamedPolygon('AC_N') Or  IsNamedPolygon('C113_2') Or  IsNamedPolygon('Earth') Or  IsNamedPolygon('F100_2') Or  IsNamedPolygon('C107_1') Or  IsNamedPolygon('Earth') Or  IsNamedPolygon('F100_2') Or  IsNamedPolygon('-BRDG_N') Or  IsNamedPolygon('-BRDG_N') Or  IsNamedPolygon('-BRDG_N') Or  IsNamedPolygon('-BRDG_N') Or  IsNamedPolygon('-BRDG_N') Or  IsNamedPolygon('AC_L') Or  IsNamedPolygon('C109_1') Or  IsNamedPolygon('AC_N') Or  IsNamedPolygon('C109_1') Or  IsNamedPolygon('F100_2') Or  IsNamedPolygon('-BRDG_N') Or  IsNamedPolygon('AC_N') Or  IsNamedPolygon('C109_1') Or  IsNamedPolygon('C107_1') Or  IsNamedPolygon('Earth') Or  IsNamedPolygon('C109_1') Or  IsNamedPolygon('AC_N') Or  IsNamedPolygon('F100_2') Or  IsNamedPolygon('Earth') Or  IsNamedPolygon('Earth') Or  IsNamedPolygon('C107_1') Or  IsNamedPolygon('AC_N') Or  IsNamedPolygon('F100_2') Or  IsNamedPolygon('C109_1') Or  IsNamedPolygon('AC_N') Or  IsNamedPolygon('C107_1')] p6: connectstyle=Direct reliefconductorwidth=10 reliefentries=4 polygonreliefangle="90 Angle" airgapwidth=10
PolygonConnect PolygonConnect_20 [All vs IsNamedPolygon('12VP') Or  IsNamedPolygon('C110_2') Or  IsNamedPolygon('C110_2') Or  IsNamedPolygon('-BRDG_N') Or  IsNamedPolygon('C113_2') Or  IsNamedPolygon('-BRDG_N') Or  IsNamedPolygon('F100_2') Or  IsNamedPolygon('C113_2') Or  IsNamedPolygon('-BRDG_N') Or  IsNamedPolygon('AC_N') Or  IsNamedPolygon('C110_2') Or  IsNamedPolygon('C110_2') Or  IsNamedPolygon('C113_2') Or  IsNamedPolygon('AC_N') Or  IsNamedPolygon('AC_N') Or  IsNamedPolygon('C113_2') Or  IsNamedPolygon('AC_N') Or  IsNamedPolygon('F100_2') Or  IsNamedPolygon('C113_2') Or  IsNamedPolygon('-BRDG_N') Or  IsNamedPolygon('-BRDG_N') Or  IsNamedPolygon('F100_2') Or  IsNamedPolygon('F100_2') Or  IsNamedPolygon('AC_N') Or  IsNamedPolygon('C113_2') Or  IsNamedPolygon('F100_2') Or  IsNamedPolygon('F100_2') Or  IsNamedPolygon('AC_N') Or  IsNamedPolygon('AC_N') Or  IsNamedPolygon('-BRDG_N') Or  IsNamedPolygon('Earth') Or  IsNamedPolygon('C107_1') Or  IsNamedPolygon('Earth') Or  IsNamedPolygon('C107_1') Or  IsNamedPolygon('Earth') Or  IsNamedPolygon('C109_1') Or  IsNamedPolygon('C109_1') Or  IsNamedPolygon('C107_1') Or  IsNamedPolygon('C109_1') Or  IsNamedPolygon('C107_1') Or  IsNamedPolygon('C109_1') Or  IsNamedPolygon('C109_1') Or  IsNamedPolygon('Earth') Or  IsNamedPolygon('C107_1') Or  IsNamedPolygon('C107_1') Or  IsNamedPolygon('Earth') Or  IsNamedPolygon('C109_1') Or  IsNamedPolygon('C109_2') Or  IsNamedPolygon('C109_2') Or  IsNamedPolygon('C110_2') Or  IsNamedPolygon('C110_2') Or  IsNamedPolygon('C109_2') Or  IsNamedPolygon('C109_2') Or  IsNamedPolygon('5VS') Or  IsNamedPolygon('C109_2') Or  IsNamedPolygon('D106_1') Or  IsNamedPolygon('C109_2')] p7: connectstyle=Direct reliefconductorwidth=10 reliefentries=4 polygonreliefangle="90 Angle" airgapwidth=10
PolygonConnect PolygonConnect_19 [All vs IsNamedPolygon('C107_1') Or  IsNamedPolygon('C107_1') Or  IsNamedPolygon('C109_1') Or  IsNamedPolygon('C107_1') Or  IsNamedPolygon('C109_1') Or  IsNamedPolygon('C107_1') Or  IsNamedPolygon('F100_2') Or  IsNamedPolygon('C109_1') Or  IsNamedPolygon('C107_1') Or  IsNamedPolygon('C107_1') Or  IsNamedPolygon('C109_1') Or  IsNamedPolygon('C109_1') Or  IsNamedPolygon('C109_1') Or  IsNamedPolygon('12VP') Or  IsNamedPolygon('C109_2') Or  IsNamedPolygon('F100_2') Or  IsNamedPolygon('F100_2') Or  IsNamedPolygon('-BRDG_N') Or  IsNamedPolygon('AC_N') Or  IsNamedPolygon('AC_N') Or  IsNamedPolygon('F100_2') Or  IsNamedPolygon('AC_N') Or  IsNamedPolygon('C113_2') Or  IsNamedPolygon('C110_2') Or  IsNamedPolygon('AC_N') Or  IsNamedPolygon('C113_2') Or  IsNamedPolygon('C110_2') Or  IsNamedPolygon('5VS') Or  IsNamedPolygon('C109_2') Or  IsNamedPolygon('C113_2') Or  IsNamedPolygon('AC_N') Or  IsNamedPolygon('-BRDG_N') Or  IsNamedPolygon('F100_2') Or  IsNamedPolygon('C109_2') Or  IsNamedPolygon('-BRDG_N') Or  IsNamedPolygon('D106_1') Or  IsNamedPolygon('C110_2') Or  IsNamedPolygon('C113_2') Or  IsNamedPolygon('C109_2') Or  IsNamedPolygon('C110_2') Or  IsNamedPolygon('C109_2') Or  IsNamedPolygon('-BRDG_N') Or  IsNamedPolygon('C110_2') Or  IsNamedPolygon('AC_N') Or  IsNamedPolygon('C113_2') Or  IsNamedPolygon('F100_2') Or  IsNamedPolygon('C109_2') Or  IsNamedPolygon('C113_2') Or  IsNamedPolygon('-BRDG_N') Or  IsNamedPolygon('AC_N') Or  IsNamedPolygon('C110_2') Or  IsNamedPolygon('-BRDG_N')] p8: connectstyle=Direct reliefconductorwidth=10 reliefentries=4 polygonreliefangle="90 Angle" airgapwidth=10
PolygonConnect PolygonConnect_18 [All vs IsNamedPolygon('C109_2') Or  IsNamedPolygon('C109_2') Or  IsNamedPolygon('D106_1') Or  IsNamedPolygon('C109_2') Or  IsNamedPolygon('C110_2') Or  IsNamedPolygon('C110_2') Or  IsNamedPolygon('C109_2') Or  IsNamedPolygon('C109_2') Or  IsNamedPolygon('5VS') Or  IsNamedPolygon('C109_2') Or  IsNamedPolygon('F100_2') Or  IsNamedPolygon('AC_N') Or  IsNamedPolygon('AC_N') Or  IsNamedPolygon('-BRDG_N') Or  IsNamedPolygon('-BRDG_N') Or  IsNamedPolygon('C113_2') Or  IsNamedPolygon('-BRDG_N') Or  IsNamedPolygon('C110_2') Or  IsNamedPolygon('C113_2') Or  IsNamedPolygon('AC_N') Or  IsNamedPolygon('AC_N') Or  IsNamedPolygon('AC_N') Or  IsNamedPolygon('AC_N') Or  IsNamedPolygon('-BRDG_N') Or  IsNamedPolygon('C113_2') Or  IsNamedPolygon('C110_2') Or  IsNamedPolygon('F100_2') Or  IsNamedPolygon('C113_2') Or  IsNamedPolygon('AC_N') Or  IsNamedPolygon('F100_2') Or  IsNamedPolygon('C113_2') Or  IsNamedPolygon('C109_1') Or  IsNamedPolygon('F100_2') Or  IsNamedPolygon('C109_1') Or  IsNamedPolygon('-BRDG_N') Or  IsNamedPolygon('F100_2') Or  IsNamedPolygon('C113_2') Or  IsNamedPolygon('C110_2') Or  IsNamedPolygon('F100_2') Or  IsNamedPolygon('-BRDG_N') Or  IsNamedPolygon('C110_2') Or  IsNamedPolygon('C109_1') Or  IsNamedPolygon('C109_1') Or  IsNamedPolygon('C109_1') Or  IsNamedPolygon('C109_1') Or  IsNamedPolygon('12VP')] p9: connectstyle=Direct reliefconductorwidth=10 reliefentries=4 polygonreliefangle="90 Angle" airgapwidth=10
PolygonConnect PolygonConnect_17 [All vs IsNamedPolygon('AC_N') Or  IsNamedPolygon('-BRDG_N') Or  IsNamedPolygon('F100_2') Or  IsNamedPolygon('-BRDG_N') Or  IsNamedPolygon('-BRDG_N') Or  IsNamedPolygon('F100_2') Or  IsNamedPolygon('AC_N') Or  IsNamedPolygon('F100_2') Or  IsNamedPolygon('-BRDG_N') Or  IsNamedPolygon('F100_2') Or  IsNamedPolygon('AC_N') Or  IsNamedPolygon('F100_2') Or  IsNamedPolygon('-BRDG_N') Or  IsNamedPolygon('AC_N') Or  IsNamedPolygon('-BRDG_N') Or  IsNamedPolygon('F100_2') Or  IsNamedPolygon('C113_2') Or  IsNamedPolygon('D106_1') Or  IsNamedPolygon('C113_2') Or  IsNamedPolygon('AC_N') Or  IsNamedPolygon('C113_2') Or  IsNamedPolygon('C113_2') Or  IsNamedPolygon('C110_2') Or  IsNamedPolygon('C110_2') Or  IsNamedPolygon('C113_2') Or  IsNamedPolygon('5VS') Or  IsNamedPolygon('C109_2') Or  IsNamedPolygon('C109_2') Or  IsNamedPolygon('AC_N') Or  IsNamedPolygon('C110_2') Or  IsNamedPolygon('C113_2') Or  IsNamedPolygon('C109_2') Or  IsNamedPolygon('C110_2') Or  IsNamedPolygon('C109_2') Or  IsNamedPolygon('AC_N') Or  IsNamedPolygon('C109_2') Or  IsNamedPolygon('C110_2') Or  IsNamedPolygon('C109_2') Or  IsNamedPolygon('C110_2') Or  IsNamedPolygon('12VP')] p10: connectstyle=Direct reliefconductorwidth=10 reliefentries=4 polygonreliefangle="90 Angle" airgapwidth=10
PolygonConnect PolygonConnect_16 [All vs IsNamedPolygon('12VP') Or  IsNamedPolygon('AC_N') Or  IsNamedPolygon('C109_2') Or  IsNamedPolygon('AC_N') Or  IsNamedPolygon('AC_N') Or  IsNamedPolygon('AC_N') Or  IsNamedPolygon('C110_2') Or  IsNamedPolygon('C113_2') Or  IsNamedPolygon('C113_2') Or  IsNamedPolygon('C113_2') Or  IsNamedPolygon('C109_2') Or  IsNamedPolygon('C113_2') Or  IsNamedPolygon('5VS') Or  IsNamedPolygon('C110_2') Or  IsNamedPolygon('C110_2') Or  IsNamedPolygon('C109_2') Or  IsNamedPolygon('C109_2') Or  IsNamedPolygon('D106_1') Or  IsNamedPolygon('C110_2') Or  IsNamedPolygon('C110_2') Or  IsNamedPolygon('C113_2') Or  IsNamedPolygon('AC_N') Or  IsNamedPolygon('C109_2') Or  IsNamedPolygon('AC_N') Or  IsNamedPolygon('-BRDG_N') Or  IsNamedPolygon('C110_2') Or  IsNamedPolygon('-BRDG_N') Or  IsNamedPolygon('C109_2') Or  IsNamedPolygon('C113_2')] p11: connectstyle=Direct reliefconductorwidth=10 reliefentries=4 polygonreliefangle="90 Angle" airgapwidth=10
PolygonConnect PolygonConnect_15 [All vs IsNamedPolygon('12VP') Or  IsNamedPolygon('AC_N') Or  IsNamedPolygon('C113_2') Or  IsNamedPolygon('AC_N') Or  IsNamedPolygon('C110_2') Or  IsNamedPolygon('D106_1') Or  IsNamedPolygon('C110_2') Or  IsNamedPolygon('C113_2') Or  IsNamedPolygon('C109_2') Or  IsNamedPolygon('C113_2') Or  IsNamedPolygon('C109_2') Or  IsNamedPolygon('C113_2') Or  IsNamedPolygon('AC_N') Or  IsNamedPolygon('AC_N') Or  IsNamedPolygon('AC_N') Or  IsNamedPolygon('C109_2') Or  IsNamedPolygon('5VS') Or  IsNamedPolygon('C110_2') Or  IsNamedPolygon('C109_2') Or  IsNamedPolygon('C110_2') Or  IsNamedPolygon('C110_2') Or  IsNamedPolygon('C113_2') Or  IsNamedPolygon('C110_2') Or  IsNamedPolygon('C109_2') Or  IsNamedPolygon('C113_2') Or  IsNamedPolygon('C109_2') Or  IsNamedPolygon('AC_N')] p12: connectstyle=Direct reliefconductorwidth=10 reliefentries=4 polygonreliefangle="90 Angle" airgapwidth=10
PolygonConnect PolygonConnect_14 [All vs IsNamedPolygon('C110_2') Or  IsNamedPolygon('C110_2') Or  IsNamedPolygon('C109_2') Or  IsNamedPolygon('C113_2') Or  IsNamedPolygon('C113_2') Or  IsNamedPolygon('D106_1') Or  IsNamedPolygon('C110_2') Or  IsNamedPolygon('C113_2') Or  IsNamedPolygon('C110_2') Or  IsNamedPolygon('C109_2') Or  IsNamedPolygon('C109_2') Or  IsNamedPolygon('C109_2') Or  IsNamedPolygon('C113_2') Or  IsNamedPolygon('C113_2') Or  IsNamedPolygon('C110_2') Or  IsNamedPolygon('C110_2') Or  IsNamedPolygon('C113_2') Or  IsNamedPolygon('C109_2') Or  IsNamedPolygon('5VS') Or  IsNamedPolygon('C109_2') Or  IsNamedPolygon('12VP')] p13: connectstyle=Direct reliefconductorwidth=10 reliefentries=4 polygonreliefangle="90 Angle" airgapwidth=10
PolygonConnect PolygonConnect_13 [All vs IsNamedPolygon('C110_2') Or  IsNamedPolygon('C109_2') Or  IsNamedPolygon('D106_1') Or  IsNamedPolygon('C109_2') Or  IsNamedPolygon('C110_2') Or  IsNamedPolygon('C110_2') Or  IsNamedPolygon('C110_2') Or  IsNamedPolygon('C109_2') Or  IsNamedPolygon('C109_2') Or  IsNamedPolygon('C109_2') Or  IsNamedPolygon('C110_2') Or  IsNamedPolygon('C110_2') Or  IsNamedPolygon('C110_2') Or  IsNamedPolygon('5VS') Or  IsNamedPolygon('C109_2') Or  IsNamedPolygon('12VP')] p14: connectstyle=Direct reliefconductorwidth=10 reliefentries=4 polygonreliefangle="90 Angle" airgapwidth=10
PolygonConnect PolygonConnect_12 [All vs IsNamedPolygon('5VS') Or  IsNamedPolygon('C109_2') Or  IsNamedPolygon('D106_1') Or  IsNamedPolygon('C109_2') Or  IsNamedPolygon('C109_2') Or  IsNamedPolygon('C109_2') Or  IsNamedPolygon('C109_2') Or  IsNamedPolygon('C109_2') Or  IsNamedPolygon('12VP')] p15: connectstyle=Direct reliefconductorwidth=10 reliefentries=4 polygonreliefangle="90 Angle" airgapwidth=10
PolygonConnect PolygonConnect_11 [All vs IsNamedPolygon('D106_1') Or  IsNamedPolygon('12VP') Or  IsNamedPolygon('5VS')] p16: connectstyle=Direct reliefconductorwidth=10 reliefentries=4 polygonreliefangle="90 Angle" airgapwidth=10
PolygonConnect PolygonConnect_10 [All vs IsNamedPolygon('12VP') Or  IsNamedPolygon('D106_1')] p17: connectstyle=Direct reliefconductorwidth=10 reliefentries=4 polygonreliefangle="90 Angle" airgapwidth=10
PolygonConnect PolygonConnect_9 [All vs IsNamedPolygon('C11_1') Or  IsNamedPolygon('Vin') Or  IsNamedPolygon('Vin') Or  IsNamedPolygon('5V') Or  IsNamedPolygon('D6_2') Or  IsNamedPolygon('Q3_3') Or  IsNamedPolygon('GND2') Or  IsNamedPolygon('GND2') Or  IsNamedPolygon('GND') Or  IsNamedPolygon('Q3_4') Or  IsNamedPolygon('12V5') Or  IsNamedPolygon('GND') Or  IsNamedPolygon('12V5') Or  IsNamedPolygon('D3_1')] p18: connectstyle=Direct reliefconductorwidth=10 reliefentries=4 polygonreliefangle="90 Angle" airgapwidth=10
PolygonConnect PolygonConnect_8 [All vs IsNamedPolygon('C11_1') Or  IsNamedPolygon('Vin') Or  IsNamedPolygon('12V5') Or  IsNamedPolygon('Q3_3') Or  IsNamedPolygon('GND2') Or  IsNamedPolygon('GND2') Or  IsNamedPolygon('5V') Or  IsNamedPolygon('Q3_4') Or  IsNamedPolygon('12V5')] p19: connectstyle=Direct reliefconductorwidth=10 reliefentries=4 polygonreliefangle="90 Angle" airgapwidth=10
PolygonConnect PolygonConnect_7 [All vs IsNamedPolygon('GND2') Or  IsNamedPolygon('GND2') Or  IsNamedPolygon('5V') Or  IsNamedPolygon('12V5') Or  IsNamedPolygon('12V5') Or  IsNamedPolygon('C11_1')] p20: connectstyle=Direct reliefconductorwidth=10 reliefentries=4 polygonreliefangle="90 Angle" airgapwidth=10
PolygonConnect PolygonConnect_6 [All vs IsNamedPolygon('GND2') Or  IsNamedPolygon('SGND') Or  IsNamedPolygon('GND1') Or  IsNamedPolygon('C901_1') Or  IsNamedPolygon('SGND') Or  IsNamedPolygon('GND2') Or  IsNamedPolygon('GND1')] p21: connectstyle=Direct reliefconductorwidth=10 reliefentries=4 polygonreliefangle="90 Angle" airgapwidth=10
PolygonConnect PolygonConnect_5 [All vs IsNamedPolygon('GND1') Or  IsNamedPolygon('GND1')] p22: connectstyle=Direct reliefconductorwidth=10 reliefentries=4 polygonreliefangle="90 Angle" airgapwidth=10
PolygonConnect PolygonConnect_4 [All vs IsNamedPolygon('C21_1') Or  IsNamedPolygon('C5_1') Or  IsNamedPolygon('C12_2') Or  IsNamedPolygon('C2_2') Or  IsNamedPolygon('C13_1') Or  IsNamedPolygon('C28_1') Or  IsNamedPolygon('C6_1') Or  IsNamedPolygon('GND') Or  IsNamedPolygon('GND2') Or  IsNamedPolygon('C14_1') Or  IsNamedPolygon('C13_1') Or  IsNamedPolygon('Q1_3') Or  IsNamedPolygon('C14_1') Or  IsNamedPolygon('C5_1') Or  IsNamedPolygon('GND2') Or  IsNamedPolygon('C28_1') Or  IsNamedPolygon('D5_2') Or  IsNamedPolygon('D6_2') Or  IsNamedPolygon('D2_1') Or  IsNamedPolygon('C12_2') Or  IsNamedPolygon('D2_1') Or  IsNamedPolygon('C4_1') Or  IsNamedPolygon('C4_1') Or  IsNamedPolygon('C2_2') Or  IsNamedPolygon('GND') Or  IsNamedPolygon('C33_1') Or  IsNamedPolygon('C9_1')] p23: connectstyle=Direct reliefconductorwidth=10 reliefentries=4 polygonreliefangle="90 Angle" airgapwidth=10
PolygonConnect PolygonConnect_3 [All vs IsNamedPolygon('C28_1') Or  IsNamedPolygon('C12_2') Or  IsNamedPolygon('C28_1') Or  IsNamedPolygon('C9_1') Or  IsNamedPolygon('D5_2') Or  IsNamedPolygon('C12_2') Or  IsNamedPolygon('C2_2') Or  IsNamedPolygon('C14_1') Or  IsNamedPolygon('C4_1') Or  IsNamedPolygon('C14_1') Or  IsNamedPolygon('D6_2') Or  IsNamedPolygon('GND2') Or  IsNamedPolygon('Q1_3') Or  IsNamedPolygon('C5_1') Or  IsNamedPolygon('D2_1') Or  IsNamedPolygon('C4_1') Or  IsNamedPolygon('C13_1') Or  IsNamedPolygon('C5_1') Or  IsNamedPolygon('C13_1') Or  IsNamedPolygon('C33_1') Or  IsNamedPolygon('D2_1') Or  IsNamedPolygon('GND') Or  IsNamedPolygon('GND') Or  IsNamedPolygon('GND2') Or  IsNamedPolygon('C2_2') Or  IsNamedPolygon('C6_1') Or  IsNamedPolygon('C21_1')] p24: connectstyle=Direct reliefconductorwidth=10 reliefentries=4 polygonreliefangle="90 Angle" airgapwidth=10
PolygonConnect PolygonConnect_2 [All vs IsNamedPolygon('C21_1') Or  IsNamedPolygon('C4_1') Or  IsNamedPolygon('D5_2') Or  IsNamedPolygon('C5_1') Or  IsNamedPolygon('C14_1') Or  IsNamedPolygon('C13_1') Or  IsNamedPolygon('C4_1') Or  IsNamedPolygon('C33_1') Or  IsNamedPolygon('C12_2') Or  IsNamedPolygon('D2_1') Or  IsNamedPolygon('C2_2') Or  IsNamedPolygon('C28_1') Or  IsNamedPolygon('C12_2') Or  IsNamedPolygon('D2_1') Or  IsNamedPolygon('C5_1') Or  IsNamedPolygon('Q1_3') Or  IsNamedPolygon('GND') Or  IsNamedPolygon('D6_2') Or  IsNamedPolygon('C6_1') Or  IsNamedPolygon('C2_2') Or  IsNamedPolygon('C14_1') Or  IsNamedPolygon('C28_1') Or  IsNamedPolygon('C13_1') Or  IsNamedPolygon('C9_1') Or  IsNamedPolygon('GND')] p25: connectstyle=Direct reliefconductorwidth=10 reliefentries=4 polygonreliefangle="90 Angle" airgapwidth=10
PolygonConnect PolygonConnect_1 [All vs IsNamedPolygon('C28_1') Or  IsNamedPolygon('D5_2') Or  IsNamedPolygon('C5_1') Or  IsNamedPolygon('C5_1') Or  IsNamedPolygon('D2_1') Or  IsNamedPolygon('C21_1') Or  IsNamedPolygon('C9_1') Or  IsNamedPolygon('C4_1') Or  IsNamedPolygon('C14_1') Or  IsNamedPolygon('C28_1') Or  IsNamedPolygon('C6_1') Or  IsNamedPolygon('C12_2') Or  IsNamedPolygon('C33_1') Or  IsNamedPolygon('C4_1') Or  IsNamedPolygon('C13_1') Or  IsNamedPolygon('C12_2') Or  IsNamedPolygon('D6_2') Or  IsNamedPolygon('C2_2') Or  IsNamedPolygon('C14_1') Or  IsNamedPolygon('D2_1') Or  IsNamedPolygon('C2_2') Or  IsNamedPolygon('C13_1')] p26: connectstyle=Direct reliefconductorwidth=10 reliefentries=4 polygonreliefangle="90 Angle" airgapwidth=10
PolygonConnect [All] p27: connectstyle=Direct reliefconductorwidth=10 reliefentries=4 polygonreliefangle="90 Angle" airgapwidth=10
RoutingVias ThermalPadVias [IsVia and InAnyComponent] p1: holewidth=7.87 width=19.68 viastyle="Through Hole" minholewidth=7.87 minwidth=19.68 maxholewidth=12.99 maxwidth=23.62
RoutingVias [All] p2: holewidth=16 width=34 viastyle="Through Hole" minholewidth=7.87 minwidth=20 maxholewidth=40 maxwidth=65
SilkToBoardRegionClearance [Not ((IsComment or IsDesignator) And (Hide <> 'False')) and not InRegion(1000,500,4000,800)] p1:
SilkToSilkClearance SilkToSilkClearance_Pb-FreeLogo [(HasFootprint('Pb-Free_Overlay_Medium') OR HasFootprint('Pb-Free_Overlay_Small')) vs (HasFootprint('Pb-Free_Overlay_Medium') OR HasFootprint('Pb-Free_Overlay_Small'))] p1: silktosilkclearance=0
SilkToSilkClearance [All] p2: silktosilkclearance=1
SilkToSolderMaskClearance "Silk to Solder Mask Opening" [All] p1: minsilkscreentomaskgap=1 clearancetoexposedcopper=FALSE
SolderMaskExpansion [All] p1: expansion=1.97 istentingtop=FALSE
Width [All] p1: maxlimit=100 minlimit=6 preferedwidth=10 checkconnectedcopper=TRUE
14 further rules are at their usual default settings.

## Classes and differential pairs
net class HV_AC_N: AC_N AC_N1 N_Wire Neutral
net class HV_SW: SW1 SW2
net class MV_DC: NetR602_1 NetR606_1
net class MV_AC_N: NetR604_1 NetR608_1
net class HV_AC_LF_SW: +BRDG_N -BRDG_N NetD103_1 NetR102_2 VDDB
net class HV_DC: 12V_inrush DRV_Relay NetQ101_1 NetQ106_1 NetR119_2 Vbulk Vbulk_out
net class HV_AC_L: AC_L AC_L1 L_Wire Vcb
net class MV_AC_L: NetR603_1 NetR607_1 NetR621_1 NetR622_1
component class PCB_Project_PMP40988_Main_Board_E3_Power: !PCB101 C1 C2 C3 C4 C5 C101 C102 C104 C105 C106 C108 C109 C110 C111 C112 C113 C114 C115 C116 C117 C118 C119 C120 C122 C123 C124 C126 C127 C128 C130 C131 D101 D102 D103 D104 D105 D106 D107 J1 J2 J6 J7 J101 L1 L2 L102 L103 L104 L106 L? N_LF_1 N_LF_2 NT1 PGND_LF_1 PGND_LF_2 PGND_PH1_1 PGND_PH1_2 PGND_PH2_1 PGND_PH2_2 Q101 Q106 R101 R102 R103 R104 R105 R106 R107 R108 R109 R110 R111 R112 R113 R114 R117 R118 R119 R120 R121 R122 RT1 SW_PH1_1 SW_PH1_2 SW_PH2_1 SW_PH2_2 TP101 TP103 U1 U101 U103 VB_LF_1 VB_LF_2 VB_PH1_1 VB_PH1_2 VB_PH2_1 VB_PH2_2
component class PCB_Project_PMP40988_Main_Board_E3_Control: C601 C603 C604 C605 C606 C608 C609 C610 C612 C613 C614 C615 C616 C619 C620 C621 C622 C623 C624 J01 J3 J8 J9 J601 J602 J604 L601 LOGO601 LOGO602 Logo603 Logo604 R1 R601 R602 R603 R604 R606 R607 R608 R609 R610 R611 R612 R613 R614 R615 R616 R617 R618 R619 R620 R621 R622 R623 R624 R625 R626 R632 R637 R640 R641 R642 R643 U601 U604 U605

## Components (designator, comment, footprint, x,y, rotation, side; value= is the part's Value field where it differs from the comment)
C1 "GMK107BJ105KA-T" 0603 5178,2084 r270 bottom value=1uF
C2 "C2225C154KDRAC7800" FP-C2225C154KDRAC7800_2225-MFG 5700,666 r90 top value=150nF
C3 "C2225C154KDRAC7800" FP-C2225C154KDRAC7800_2225-MFG 7888,723 r270 top value=150nF
C4 "C2225C154KDRAC7800" FP-C2225C154KDRAC7800_2225-MFG 7622,723 r270 top value=150nF
C5 "C2225C154KDRAC7800" FP-C2225C154KDRAC7800_2225-MFG 5432,666 r90 top value=150nF
C101 "GRM32DR72J473KW01L" 1210_220 10139,2029 r90 bottom value=0.047uF
C102 "GRM32DR72J473KW01L" 1210_220 10270,2029 r90 bottom value=0.047uF
C104 "DE2E3SA102MN3AY02F" Y_CAP 2078,2214 r0 top value=1000pF
C105 "DE2E3SA102MN3AY02F" Y_CAP 1500,366 r270 top value=1000pF
C106 "R523I347050P3K" FP-R523I347050P3K_RADIAL-MFG 5809,156 r180 top value=470nF
C108 "2.2uF" WCAP-FTXX_L26W15H25 2196,2036 r90 top
C109 "2.2uF" WCAP-FTXX_L26W15H25 1703,299 r180 top
C110 "R523I347050P3K" FP-R523I347050P3K_RADIAL-MFG 7385,156 r180 top value=470nF
C111 "DE2E3SA102MN3AY02F" Y_CAP 2075,1834 r0 top value=1000pF
C112 "DE2E3SA102MN3AY02F" Y_CAP 1883,366 r270 top value=1000pF
C113 "CC0402KRX7R8BB104" 0402#1 2663,1947 r90 bottom value=0.1uF
C114 "GRM185R60J105KE26D" 0603 2608,1959 r90 bottom value=1uF
C115 "GRM155R60J102KA01D" 0402#1 2758,1947 r90 bottom value=1000pF
C116 "C2012X5R1C226M125AC" 0805_HV 4500,1341 r0 bottom value=22uF
C117 "CC0402MRX5R6BB105" 0402#1 4429,1716 r90 bottom value=1uF
C118 "C2012X5R1C226M125AC" 0805_HV 4500,1262 r0 bottom value=22uF
C119 "C1608X7R1E105K080AB" 0603 4486,1412 r180 bottom value=1uF
C120 "CC0402KRX7R8BB104" 0402#1 5274.62,2352 r0 bottom value=0.1uF
C122 "C0402C102K5RACTU" 0402#1 4279,1718 r90 bottom value=1000pF
C123 "C0402C102K5RACTU" 0402#1 4374,1718 r90 bottom value=1000pF
C124 "R523I347050P3K" FP-R523I347050P3K_RADIAL-MFG 6616,156 r0 top value=470nF
C126 "C2012X5R1C226M125AC" 0805_HV 4315,1404 r0 bottom value=22uF
C127 "CC0402KRX7R8BB472" 0402#1 4482,1716 r90 bottom value=4700pF
C128 "C0402C102K5RACTU" 0402#1 5438,2250 r90 bottom value=1000pF
C130 "C1812W104KDRACTU" 1812_254 5754,446 r180 bottom value=0.1uF
C131 "C1812W104KDRACTU" 1812_254 7533,952 r0 bottom value=0.1uF
C601 "GRM155R70J104KA01D" 0402#1 6287,1499.49 r90 bottom value=0.1uF
C603 "C1005X5R1A473K050BA" 0402#1 6476,1294.49 r0 bottom value=0.047uF
C604 "CC0402KRX7R9BB221" 0402#1 6730,1292.49 r180 bottom value=220pF
C605 "CC0402KRX7R9BB221" 0402#1 6579,1246.49 r180 bottom value=220pF
C606 "CC0402KRX7R9BB221" 0402#1 6373,1246.49 r180 bottom value=220pF
C608 "C1005X5R1A473K050BA" 0402#1 6250,1274.49 r90 bottom value=0.047uF
C609 "885012005055" 0402#1 7450,1242 r90 bottom value=10pF
C610 "C1005X5R1A473K050BA" 0402#1 6298,1274.49 r90 bottom value=0.047uF
C612 "885012005055" 0402#1 7547,1242 r90 bottom value=10pF
C613 "C1005X5R1A473K050BA" 0402#1 6654,1272.49 r90 bottom value=0.047uF
C614 "885012005055" 0402#1 7647,1242 r90 bottom value=10pF
C615 "C1005X5R1A473K050BA" 0402#1 6824,1246 r0 bottom value=0.047uF
C616 "885012005055" 0402#1 7748,1242 r90 bottom value=10pF
C619 "EEU-EB1E101S" CAPPR250W50D630H1120 10521,1400 r270 top value=100uF
C620 "C2012X7R1E475K125AB" 0805_HV 8789,1444 r90 bottom value=4.7uF
C621 "CL21A226KQQNNNE" 0805_HV 8608,1600 r0 bottom value=22uF
C622 "GRM155R61E225ME15D" 0402#1 5985,1389.49 r270 bottom value=2.2uF
C623 "CC0402KRX7R8BB104" 0402#1 8565,1467 r90 bottom value=0.1uF
C624 "CC0402KRX7R9BB221" 0402#1 6181,1056 r180 bottom value=220pF
D101 "VS-15EVL06-M3/I" DPAK 5067,846 r90 bottom value=600V
D102 "VS-15EVL06-M3/I" DPAK 4670,991 r0 bottom value=600V
D103 "BAT54WS-7-F" SOD-323 4745,1315 r270 bottom value=30V
D104 "VS-15EVL06-M3/I" DPAK 3807.24,866.14 r270 bottom value=600V
D105 "VS-15EVL06-M3/I" DPAK 4189,964 r0 bottom value=600V
D106 "BAT54WS-7-F" SOD-323 4357,1311 r270 bottom value=30V
D107 "MURA160T3G" SMA 4675,1641 r90 bottom value=600V
J1 "M50-3000645" FP-M50-3000645_HDR12-MFG 6515,388 r0 top
J01 "M52-040023V0345" FP-M52-040023V0345_HDR3-MFG 5734,2490 r180 bottom
J2 "M50-3000645" FP-M50-3000645_HDR12-MFG 6775,1013 r180 top
J3 "M52-040023V0345" FP-M52-040023V0345_HDR3-MFG 8293,2489 r180 bottom
J6 "M50-3030242" FP-M50-3030242_HDR2-MFG 4764,1212 r180 top
J7 "M50-3030242" FP-M50-3030242_HDR2-MFG 4237,1209 r180 top
J8 "SSW-103-02-G-D" FP-SSW-103-02-G-D_RCPT6-MFG 10555,945 r90 top
J9 "SSW-102-02-G-D" FP-SSW-102-02-G-D_HDR4-MFG 10555,195.5 r270 top
J101 "282856-3" TE_282856-3 10564,2159.15 r90 top
J601 "M52-040023V2045" FP-M52-040023V2045_HDR20-MFG 6425,1159.97 r0 bottom
J602 "M52-040023V2045" FP-M52-040023V2045_HDR20-MFG 7575,1159.97 r0 bottom
J604 "691214110002" Wurth_691214110002 10532,1705.1 r90 top
L1 "PAL6493.144NL" FP-PAL6493.144NL_PTH_IND_36MM0_33MM0-MFG 3068,652 r180 top value=140uH
L2 "PAL6493.144NL" FP-PAL6493.144NL_PTH_IND_36MM0_33MM0-MFG 9610,678 r180 top value=140uH
L102 "86H-22021C" FP-86H-22021C_PTH_IND_30MM0_14MM2-MFG 4388,333 r180 top value=16.2uH
L103 "ARCDC302030E282N2B" FP-ARCDC302030E282N2B_PTH_30MM0_20MM0-MFG 1703,991 r90 top
L104 "86H-22021C" FP-86H-22021C_PTH_IND_30MM0_14MM2-MFG 8573,665 r90 top value=16.2uH
L106 "YXS80660T" FP-YXS80660T_PTH_30MM0_19MM0-MFG 1515,1986 r270 top
L601 "74438336100" WE-MAPI_3020 8471,1441 r90 top value=10uH
LOGO601 "CAUTION HOT SURFACE" IEC_HotSurface_Small 4215,939 r0 top
LOGO602 "DANGER HIGH VOLTAGE" IEC_HighVoltage_Small 950,1689 r0 top
Logo603 "FCC disclaimer" FCC_disclaimer 8536,2517 r180 bottom
Logo604 "WEEE logo" WEEE_Minimum 9322,2412 r180 bottom
N_LF_1 "0312-0-15-15-34-27-10-0" Mill-Max_0312-0-15-15-34-27-10-0 4563,1161 r270 top
N_LF_2 "0312-0-15-15-34-27-10-0" Mill-Max_0312-0-15-15-34-27-10-0 4427,1161 r270 top
NT1 "Net-Tie" Net-Tie_50milWide_30milLong 10734,1815 r270 top net-tie
PGND_LF_1 "0312-0-15-15-34-27-10-0" Mill-Max_0312-0-15-15-34-27-10-0 4063,1161 r270 top
PGND_LF_2 "0312-0-15-15-34-27-10-0" Mill-Max_0312-0-15-15-34-27-10-0 3927,1161 r270 top
PGND_PH1_1 "0312-0-15-15-34-27-10-0" Mill-Max_0312-0-15-15-34-27-10-0 5600,455 r90 top
PGND_PH1_2 "0312-0-15-15-34-27-10-0" Mill-Max_0312-0-15-15-34-27-10-0 5445,455 r90 top
PGND_PH2_1 "0312-0-15-15-34-27-10-0" Mill-Max_0312-0-15-15-34-27-10-0 7690,946 r270 top
PGND_PH2_2 "0312-0-15-15-34-27-10-0" Mill-Max_0312-0-15-15-34-27-10-0 7845,946 r270 top
Q101 "IPT60R022S7XTMA1" FP-IPT60R080G7XTMA1_HSOF-8-MFG 5692,1567 r0 bottom
Q106 "IPT60R022S7XTMA1" FP-IPT60R080G7XTMA1_HSOF-8-MFG 5292,1567 r0 bottom
R1 "ERJ-H3G0R00V" FP-ERJ-H3G0R00V_0603-MFG 10728,72 r0 top value=0
R101 "RC0603FR-071RL" 0603 5144,1912 r180 bottom value=1.00
R102 "RC0603FR-0710RL" 0603 4733,1406 r0 bottom value=10.0
R103 "RC0603FR-0710KL" 0603 5550,1850 r180 bottom value=10.0k
R104 "RC0603FR-071RL" 0603 5482,1917 r0 bottom value=1.00
R105 "RC0603FR-071KL" 0603 4806,1307 r90 bottom value=1.00k
R106 "RC0603FR-0710KL" 0603 5146,1850 r180 bottom value=10.0k
R107 "RC1206FR-07100KL" 1206 995,2157 r90 bottom value=100k
R108 "RC1206FR-07100KL" 1206 1196,2157 r90 bottom value=100k
R109 "RC1206FR-07100KL" 1206 995,1961 r90 bottom value=100k
R110 "RC1206FR-07100KL" 1206 1196,1961.51 r90 bottom value=100k
R111 "RC0603FR-0710RL" 0603 4257,1334 r180 bottom value=10.0
R112 "RC1206FR-07100KL" 1206 995,1766 r90 bottom value=100k
R113 "RC1206FR-07100KL" 1206 1196,1766 r90 bottom value=100k
R114 "RC0603FR-071KL" 0603 4257,1275 r180 bottom value=1.00k
R117 "RC0603FR-0720RL" 0603 4675,1828 r90 bottom value=20.0
R118 "CRCW04021K00JNED" 0402#2 4235,1716 r90 bottom value=1.0k
R119 "RC0603FR-075R11L" 0603 5320,2002 r0 bottom value=5.11
R120 "CRCW04021K00JNED" 0402#1 4326,1717 r90 bottom value=1.0k
R121 "RC0402FR-071ML" 0402#1 4542,1715 r270 bottom value=1.00Meg
R122 "CRCW04021K00JNED" 0402#1 5146,2349 r90 bottom value=1.0k
R601 "RT0402FRE074K3L" 0402#1 6263,1576.49 r180 bottom value=4.3k
R602 "RC1206FR-071ML" 1206 7135,1399 r0 bottom value=1.00Meg
R603 "RC1206FR-071ML" 1206 6926,1559 r0 bottom value=1.00Meg
R604 "RC1206FR-071ML" 1206 6926,1690 r0 bottom value=1.00Meg
R606 "RC1206FR-071ML" 1206 6978,1399 r0 bottom value=1.00Meg
R607 "RC1206FR-071ML" 1206 6770,1559 r0 bottom value=1.00Meg
R608 "RC1206FR-071ML" 1206 6770,1690 r0 bottom value=1.00Meg
R609 "CRCW04025K11FKED" 0402#1 6084,1553.49 r270 bottom value=5.11k
R610 "CRCW040210K0FKED" 0402#1 6060,1477.49 r0 bottom value=10.0k
R611 "RC0402FR-07100RL" 0402#1 6287,1396.49 r90 bottom value=100
R612 "RC1206FR-071ML" 1206 6814,1399 r0 bottom value=1.00Meg
R613 "RC1206FR-071ML" 1206 6614,1559 r0 bottom value=1.00Meg
R614 "RC1206FR-071ML" 1206 6614,1690 r0 bottom value=1.00Meg
R615 "ERA-2AEB4871X" 0402#1 6476,1246.49 r180 bottom value=4.87k
R616 "CRCW04020000Z0ED" 0402#1 6060,1429.49 r180 bottom value=0
R617 "CRCW040218K0FKED" 0402#1 6730,1244.49 r0 bottom value=18.0k
R618 "CRCW040218K0FKED" 0402#1 6579,1294.49 r0 bottom value=18.0k
R619 "CRCW040218K0FKED" 0402#1 6373,1294.49 r0 bottom value=18.0k
R620 "RC0402FR-0715KL" 0402#1 6295,1069 r90 bottom value=15.0k
R621 "RC1206FR-071ML" 1206 9705,265 r270 bottom value=1.00Meg
R622 "RC1206FR-071ML" 1206 9702,451 r270 bottom value=1.00Meg
R623 "RC0402FR-0715KL" 0402#1 6354,1072 r90 bottom value=15.0k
